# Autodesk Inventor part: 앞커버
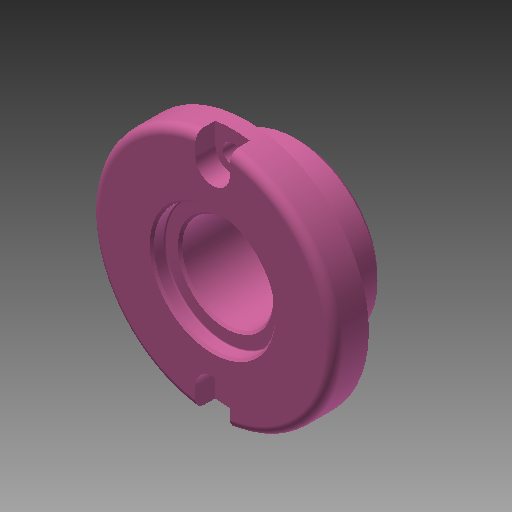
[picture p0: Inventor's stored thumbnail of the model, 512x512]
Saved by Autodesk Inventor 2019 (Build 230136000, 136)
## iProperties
Created: 2022-03
Part Number: 앞커버
Material: 일반
Document SubType Name: Modeling
Designer: mdu-01
Density: 1 g/cm^3
Appearance: 분홍색
Author: mdu-01
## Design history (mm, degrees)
sketch "스케치1"
  geometry: L1 (0, 0)-(0, -20); L2 (14, 0)-(28, 0); L3 (28, 0)-(28, -8); L4 (28, -8)-(19, -8); L5 (19, -8)-(19, -20); L6 (19, -20)-(10.5, -20); L7 (14, 0)-(14, -3); L8 (14, -3)-(10.5, -3); L9 (10.5, -3)-(10.5, -20)
  constraints: 18 end point, 5 perpendicular, 2 horizontal alignment, 2 parallel, 1 horizontal, 1 vertical
  dimensions: "d0" = 56 diameter of L3 L1; "d2" = 38 diameter of L5 L1; "d3" = 8 distance of L2.end L3.end; "d4" = 20 distance between parallel lines of L2 L6; "d5" = 21 diameter of L9 L1; "d6" = 28 diameter of L7 L1; "d7" = 3 distance of L2.start L7.end
revolve "회전1" sketch "스케치1" stored, may be unused: angle "d8" = 90 deg
fillet "모깎기1" dims "d9" = 0.5
chamfer "모따기1" distance "d10" = 0.5; stored, may be unused: second distance "d11" = 2, angle "d12" = 45 deg
chamfer "모따기2" distance "d13" = 1; stored, may be unused: second distance "d14" = 2, angle "d15" = 45 deg
fillet "모깎기2" dims "d32" = 2
sketch "스케치2" dims "d16" = 46
  geometry: 3 further points
  constraints: 2 vertical alignment, 1 coincident, 2 other
hole "구멍1" sketch "스케치2" at (0, 23) diameter "d18" = 4.5; stored, may be unused: countersink angle "d22" = 90 deg, drill point angle "d24" = 118 deg; dims "d19" = 6, "d20" = 8, "d21" = 4.6, "d23" = 8
sketch "스케치3"
  geometry: L1 (4, 23)-(4, 27.713); L2 (-4, 23)-(-4, 27.713); A1 r 4 centre (0, 23) between (-4, 23) and (4, 23) reference; A2 r 28 centre (0, 0) between (4, 27.713) and (-4, 27.713) reference; 1 further point
  constraints: 4 end point, 4 point on circle, 2 tangent, 1 parallel, 1 vertical
extrude "돌출1" cut sketch "스케치3" stored distance "d27" = 10; taper "d28" = 0 deg
fillet "모깎기3" dims "d33" = 0.3
node "솔리드1"
pattern_circular "원형 패턴1" dims angle "d30" = 360 deg
